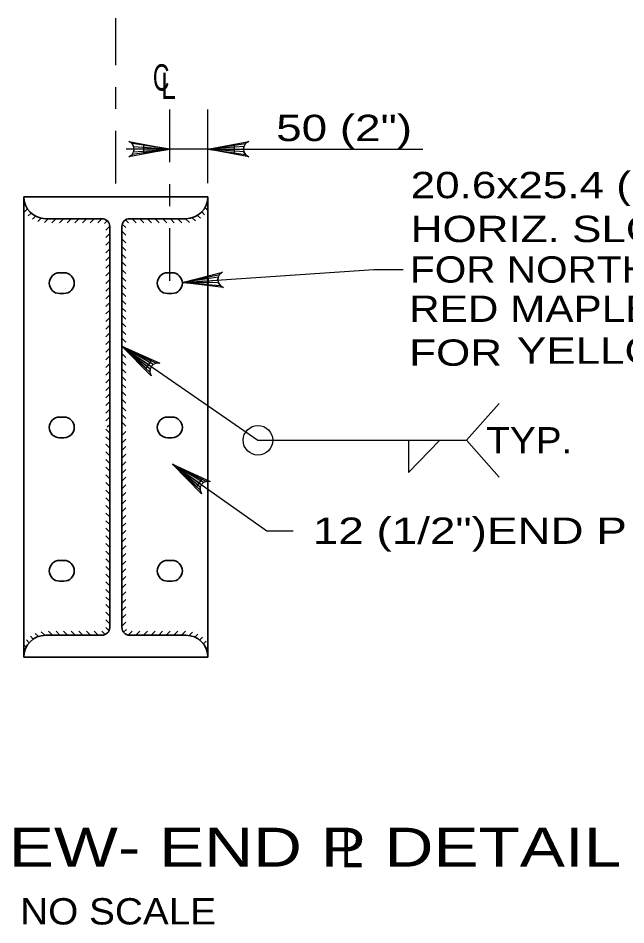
# Model space of a CAD drawing. Extents: x -11 to 79, y -154 to 0.
# Drawn here: x 56.975 to 59.744, y -56.841 to -52.709 of the extents above; entities that cross this region are included whole.
import ezdxf
from ezdxf.enums import TextEntityAlignment as Align

# ---------------------------------------------------------------- set-up
doc = ezdxf.new("R2010")
doc.units = 0
doc.header["$LTSCALE"] = 0.048
doc.linetypes.add('DOT_DASHED', pattern=[7.7, 5, -1.2, 0.3, -1.2])
doc.layers.add('3', color=7, linetype='Continuous', lineweight=25)
doc.layers.add('4', color=7, linetype='Continuous', lineweight=25)

msp = doc.modelspace()

# ---------------------------------------------------------------- hatches: boundary and pattern name
at = {"layer": '3'}
for points in [[(57.546, -53.28558), (57.546, -53.32558), (57.666, -53.30558)], [(57.95925, -53.28558), (57.95925, -53.32558), (57.83925, -53.30558)], [(57.723, -53.91358), (57.84342, -53.91533), (57.84208, -53.89542)], [(57.55825, -54.30467), (57.58133, -54.272), (57.47183, -54.219)], [(57.7895, -54.84425), (57.81258, -54.81158), (57.70308, -54.75867)]]:
    msp.add_hatch(color=256, dxfattribs=at).paths.add_polyline_path(points)

# ---------------------------------------------------------------- linework, layer by layer
at = {"layer": '3', "linetype": 'DOT_DASHED'}
msp.add_line((57.666, -53.90508), (57.666, -53.12558), dxfattribs=at)
at = {"layer": '3'}
for p, q in [((57.83925, -53.46017), (57.83925, -53.12558)), ((57.83925, -53.30558), (57.46642, -53.30558)), ((57.95925, -53.30558), (58.07925, -53.30558)), ((58.07925, -53.30558), (58.8185, -53.30558)), ((57.723, -53.91358), (58.59592, -53.85375)), ((58.59592, -53.85375), (58.72842, -53.85375)), ((57.4475, -54.20375), (58.06767, -54.63258)), ((59.01742, -54.63258), (59.16567, -54.46475)), ((58.06767, -54.63258), (59.01742, -54.63258)), ((59.01742, -54.63258), (59.16567, -54.8005)), ((57.67775, -54.74067), (58.1075, -55.04475)), ((58.1075, -55.04475), (58.2275, -55.04475))]:
    msp.add_line(p, q, dxfattribs=at)
for points in [[(57.666, -53.30558), (57.47958, -53.3405), (57.49392, -53.33058), (57.50133, -53.31808), (57.5035, -53.30558), (57.50133, -53.29308), (57.49392, -53.28058), (57.47958, -53.27067), (57.666, -53.30558), (57.49392, -53.28058), (57.50133, -53.29308), (57.666, -53.30558), (57.5035, -53.30558), (57.50133, -53.31808), (57.666, -53.30558), (57.49392, -53.33058)], [(57.83925, -53.30558), (58.02567, -53.27067), (58.01133, -53.28058), (58.00392, -53.29308), (58.00175, -53.30558), (58.00392, -53.31808), (58.01133, -53.33058), (58.02567, -53.3405), (57.83925, -53.30558), (58.01133, -53.33058), (58.00392, -53.31808), (57.83925, -53.30558), (58.00175, -53.30558), (58.00392, -53.29308), (57.83925, -53.30558), (58.01133, -53.28058)], [(57.723, -53.91358), (57.90658, -53.866), (57.89292, -53.87692), (57.88642, -53.88983), (57.88508, -53.9025), (57.88808, -53.91483), (57.89633, -53.92675), (57.91133, -53.93567), (57.723, -53.91358), (57.89633, -53.92675), (57.88808, -53.91483), (57.723, -53.91358), (57.88508, -53.9025), (57.88642, -53.88983), (57.723, -53.91358), (57.89292, -53.87692)], [(57.4475, -54.20375), (57.62067, -54.281), (57.60325, -54.281), (57.59, -54.28708), (57.58117, -54.29617), (57.57583, -54.30767), (57.57483, -54.32217), (57.58092, -54.3385), (57.4475, -54.20375), (57.57483, -54.32217), (57.57583, -54.30767), (57.4475, -54.20375), (57.58117, -54.29617), (57.59, -54.28708), (57.4475, -54.20375), (57.60325, -54.281)], [(58.754, -54.63258), (58.754, -54.77933), (58.89542, -54.63258)], [(57.67775, -54.74067), (57.85008, -54.81983), (57.83267, -54.81967), (57.81933, -54.82558), (57.81042, -54.8345), (57.80492, -54.846), (57.80375, -54.86042), (57.80975, -54.87683), (57.67775, -54.74067), (57.80375, -54.86042), (57.80492, -54.846), (57.67775, -54.74067), (57.81042, -54.8345), (57.81933, -54.82558), (57.67775, -54.74067), (57.83267, -54.81967)]]:
    msp.add_lwpolyline(points, dxfattribs=at)
for points in [[(57.546, -53.28558), (57.546, -53.32558), (57.666, -53.30558)], [(57.95925, -53.28558), (57.95925, -53.32558), (57.83925, -53.30558)], [(57.723, -53.91358), (57.84342, -53.91533), (57.84208, -53.89542)], [(57.55825, -54.30467), (57.58133, -54.272), (57.47183, -54.219)], [(57.7895, -54.84425), (57.81258, -54.81158), (57.70308, -54.75867)]]:
    msp.add_lwpolyline(points, close=True, dxfattribs=at)
msp.add_circle((58.06763, -54.6326), 0.06746, dxfattribs=at)
at = {"layer": '4', "linetype": 'DOT_DASHED'}
msp.add_line((57.42, -53.46258), (57.42, -52.70858), dxfattribs=at)
at = {"layer": '4', "lineweight": 35}
for p, q in [((57.00067, -53.52267), (57.00067, -55.62108)), ((57.83925, -53.52267), (57.00067, -53.52267)), ((57.83925, -53.52267), (57.83925, -55.62108)), ((57.00467, -53.59142), (57.01767, -53.57842)), ((57.35683, -53.62267), (57.10067, -53.62267)), ((57.73925, -53.62267), (57.48308, -53.62267)), ((57.39242, -53.65825), (57.39242, -55.4855)), ((57.4475, -53.65825), (57.4475, -55.4855)), ((57.16408, -53.86917), (57.18375, -53.86917)), ((57.65617, -53.86917), (57.67592, -53.86917)), ((57.16408, -53.96358), (57.18375, -53.96358)), ((57.65617, -53.96358), (57.67592, -53.96358)), ((57.16408, -54.52658), (57.18375, -54.52658)), ((57.65617, -54.52658), (57.67592, -54.52658)), ((57.16408, -54.62108), (57.18375, -54.62108)), ((57.65617, -54.62108), (57.67592, -54.62108)), ((57.16408, -55.18017), (57.18375, -55.18017)), ((57.65617, -55.18017), (57.67592, -55.18017)), ((57.16408, -55.27467), (57.18375, -55.27467)), ((57.65617, -55.27467), (57.67592, -55.27467)), ((57.35683, -55.52108), (57.10067, -55.52108)), ((57.73925, -55.52108), (57.48308, -55.52108)), ((57.83925, -55.62108), (57.00067, -55.62108))]:
    msp.add_line(p, q, dxfattribs=at)
at = {"layer": '4'}
for p, q in [((57.00067, -53.52583), (57.00075, -53.52575)), ((57.00067, -53.56058), (57.00608, -53.55517)), ((57.83925, -53.54992), (57.83625, -53.54692)), ((57.021, -53.60983), (57.03383, -53.59708)), ((57.82433, -53.60458), (57.8115, -53.59183)), ((57.83925, -53.58475), (57.82633, -53.57183)), ((57.04108, -53.62467), (57.05433, -53.61133)), ((57.06517, -53.63533), (57.08, -53.6205)), ((57.09467, -53.64067), (57.11258, -53.62267)), ((57.12925, -53.64075), (57.14742, -53.62267)), ((57.16408, -53.64075), (57.18217, -53.62267)), ((57.19892, -53.64075), (57.217, -53.62267)), ((57.23367, -53.64075), (57.25183, -53.62267)), ((57.2685, -53.64075), (57.28658, -53.62267)), ((57.30325, -53.64075), (57.32142, -53.62267)), ((57.33808, -53.64075), (57.35617, -53.62267)), ((57.36842, -53.64525), (57.38125, -53.63242)), ((57.47842, -53.64142), (57.46475, -53.62775)), ((57.5125, -53.64075), (57.49442, -53.62267)), ((57.54733, -53.64075), (57.52925, -53.62267)), ((57.58217, -53.64075), (57.564, -53.62267)), ((57.61692, -53.64075), (57.59883, -53.62267)), ((57.65175, -53.64075), (57.63358, -53.62267)), ((57.6865, -53.64075), (57.66842, -53.62267)), ((57.72133, -53.64075), (57.70325, -53.62267)), ((57.75508, -53.63975), (57.738, -53.62267)), ((57.78267, -53.6325), (57.7685, -53.61833)), ((57.80542, -53.6205), (57.79233, -53.60742)), ((57.37433, -53.67417), (57.39233, -53.65608)), ((57.46567, -53.69825), (57.4475, -53.68017)), ((57.46567, -53.6635), (57.44933, -53.64717)), ((57.37433, -53.709), (57.39242, -53.69083)), ((57.46567, -53.73308), (57.4475, -53.715)), ((57.37433, -53.74375), (57.39242, -53.72567)), ((57.37433, -53.77858), (57.39242, -53.76042)), ((57.46567, -53.76792), (57.4475, -53.74975)), ((57.37433, -53.81333), (57.39242, -53.79525)), ((57.46567, -53.80267), (57.4475, -53.78458)), ((57.37433, -53.84817), (57.39242, -53.83008)), ((57.46567, -53.8375), (57.4475, -53.81933)), ((57.37433, -53.88292), (57.39242, -53.86483)), ((57.46567, -53.87225), (57.4475, -53.85417)), ((57.37433, -53.91775), (57.39242, -53.89967)), ((57.46567, -53.90708), (57.4475, -53.889)), ((57.46567, -53.94192), (57.4475, -53.92375)), ((57.37433, -53.95258), (57.39242, -53.93442)), ((57.37433, -53.98733), (57.39242, -53.96925)), ((57.46567, -53.97667), (57.4475, -53.95858)), ((57.37433, -54.02217), (57.39242, -54.004)), ((57.46567, -54.0115), (57.4475, -53.99333)), ((57.37433, -54.05692), (57.39242, -54.03883)), ((57.46567, -54.04625), (57.4475, -54.02817)), ((57.37433, -54.09175), (57.39242, -54.07367)), ((57.46567, -54.08108), (57.4475, -54.063)), ((57.37433, -54.12658), (57.39242, -54.10842)), ((57.46567, -54.11583), (57.4475, -54.09775)), ((57.46567, -54.15067), (57.4475, -54.13258)), ((57.37433, -54.16133), (57.39242, -54.14325)), ((57.46567, -54.1855), (57.4475, -54.16733)), ((57.37433, -54.19617), (57.39242, -54.178)), ((57.37433, -54.23092), (57.39242, -54.21283)), ((57.46567, -54.22025), (57.4475, -54.20217)), ((57.37433, -54.26575), (57.39242, -54.24767)), ((57.46567, -54.25508), (57.4475, -54.23692)), ((57.37433, -54.3005), (57.39242, -54.28242)), ((57.46567, -54.28983), (57.4475, -54.27175)), ((57.37433, -54.33533), (57.39242, -54.31725)), ((57.46567, -54.32467), (57.4475, -54.30658)), ((57.46567, -54.3595), (57.4475, -54.34133)), ((57.37433, -54.37017), (57.39242, -54.352)), ((57.46567, -54.39425), (57.4475, -54.37617)), ((57.37433, -54.40492), (57.39242, -54.38683)), ((57.37433, -54.43975), (57.39242, -54.42158)), ((57.46567, -54.42908), (57.4475, -54.41092)), ((57.37433, -54.4745), (57.39242, -54.45642)), ((57.46567, -54.46383), (57.4475, -54.44575)), ((57.37433, -54.50933), (57.39242, -54.49125)), ((57.46567, -54.49867), (57.4475, -54.48058)), ((57.37433, -54.54408), (57.39242, -54.526)), ((57.46567, -54.53342), (57.4475, -54.51533)), ((57.39242, -54.59942), (57.37433, -54.58133)), ((57.38133, -54.57192), (57.39242, -54.56083)), ((57.46567, -54.56825), (57.4475, -54.55017)), ((57.4475, -54.57525), (57.45092, -54.57192)), ((57.39242, -54.63425), (57.37433, -54.61608)), ((57.4475, -54.61008), (57.46567, -54.592)), ((57.4475, -54.64492), (57.46567, -54.62675)), ((57.39242, -54.669), (57.37433, -54.65092)), ((57.4475, -54.67967), (57.46567, -54.66158)), ((57.39242, -54.70383), (57.37433, -54.68567)), ((57.4475, -54.7145), (57.46567, -54.69642)), ((57.39242, -54.73858), (57.37433, -54.7205)), ((57.4475, -54.74925), (57.46567, -54.73117)), ((57.39242, -54.77342), (57.37433, -54.75533)), ((57.39242, -54.80825), (57.37433, -54.79008)), ((57.4475, -54.78408), (57.46567, -54.766)), ((57.39242, -54.843), (57.37433, -54.82492)), ((57.4475, -54.81892), (57.46567, -54.80075)), ((57.4475, -54.85367), (57.46567, -54.83558)), ((57.39242, -54.87783), (57.37433, -54.85967)), ((57.4475, -54.8885), (57.46567, -54.87033)), ((57.39242, -54.91258), (57.37433, -54.8945)), ((57.4475, -54.92325), (57.46567, -54.90517)), ((57.39242, -54.94742), (57.37433, -54.92933)), ((57.4475, -54.95808), (57.46567, -54.94)), ((57.39242, -54.98217), (57.37433, -54.96408)), ((57.39242, -55.017), (57.37433, -54.99892)), ((57.4475, -54.99283), (57.46567, -54.97475)), ((57.39242, -55.05183), (57.37433, -55.03367)), ((57.4475, -55.02767), (57.46567, -55.00958)), ((57.39242, -55.08658), (57.37433, -55.0685)), ((57.4475, -55.0625), (57.46567, -55.04433)), ((57.4475, -55.09725), (57.46567, -55.07917)), ((57.39242, -55.12142), (57.37433, -55.10325)), ((57.4475, -55.13208), (57.46567, -55.11392)), ((57.39242, -55.15617), (57.37433, -55.13808)), ((57.4475, -55.16683), (57.46567, -55.14875)), ((57.39242, -55.191), (57.37433, -55.17292)), ((57.39242, -55.22583), (57.37433, -55.20767)), ((57.4475, -55.20167), (57.46567, -55.18358)), ((57.39242, -55.26058), (57.37433, -55.2425)), ((57.4475, -55.2365), (57.46567, -55.21833)), ((57.39242, -55.29542), (57.37433, -55.27725)), ((57.4475, -55.27125), (57.46567, -55.25317)), ((57.4475, -55.30608), (57.46567, -55.28792)), ((57.39242, -55.33017), (57.37433, -55.31208)), ((57.4475, -55.34083), (57.46567, -55.32275)), ((57.39242, -55.365), (57.37433, -55.34692)), ((57.4475, -55.37567), (57.46567, -55.35758)), ((57.39242, -55.39975), (57.37433, -55.38167)), ((57.4475, -55.41042), (57.46567, -55.39233)), ((57.39242, -55.43458), (57.37433, -55.4165)), ((57.39242, -55.46942), (57.37433, -55.45125)), ((57.4475, -55.44525), (57.46567, -55.42717)), ((57.389, -55.50075), (57.37433, -55.48608)), ((57.4475, -55.48008), (57.46567, -55.46192)), ((57.455, -55.50733), (57.468, -55.49433)), ((57.04408, -55.53867), (57.03108, -55.52567)), ((57.06717, -55.52692), (57.05317, -55.51292)), ((57.09625, -55.52117), (57.07992, -55.50483)), ((57.13092, -55.52108), (57.11283, -55.503)), ((57.16575, -55.52108), (57.14767, -55.503)), ((57.20058, -55.52108), (57.18242, -55.503)), ((57.23533, -55.52108), (57.21725, -55.503)), ((57.27017, -55.52108), (57.252, -55.503)), ((57.30492, -55.52108), (57.28683, -55.503)), ((57.33975, -55.52108), (57.32167, -55.503)), ((57.37142, -55.518), (57.35642, -55.503)), ((57.47667, -55.5205), (57.49417, -55.503)), ((57.51092, -55.52108), (57.529, -55.503)), ((57.54567, -55.52108), (57.56375, -55.503)), ((57.5805, -55.52108), (57.59858, -55.503)), ((57.61525, -55.52108), (57.63342, -55.503)), ((57.65008, -55.52108), (57.66817, -55.503)), ((57.68483, -55.52108), (57.703, -55.503)), ((57.71967, -55.52108), (57.73775, -55.503)), ((57.7535, -55.52208), (57.76883, -55.50675)), ((57.78042, -55.52992), (57.79392, -55.51642)), ((57.802, -55.54317), (57.81483, -55.53033)), ((57.01158, -55.57575), (57.00067, -55.56483)), ((57.02567, -55.555), (57.01283, -55.54217)), ((57.81908, -55.56083), (57.832, -55.548)), ((57.83175, -55.583), (57.83925, -55.5755)), ((57.00258, -55.60158), (57.00067, -55.59967)), ((57.83875, -55.61083), (57.83925, -55.61033))]:
    msp.add_line(p, q, dxfattribs=at)
at = {"layer": '4', "lineweight": 35}
for centre, radius, start, end in [((57.10069, -53.52267), 0.1, 180, 270), ((57.73927, -53.52267), 0.1, 270, 0), ((57.35684, -53.65824), 0.03558, 0, 90), ((57.48311, -53.65824), 0.03558, 90, 180), ((57.16407, -53.91637), 0.04724, 90, 270), ((57.18376, -53.91637), 0.04724, 270, 90), ((57.6562, -53.91637), 0.04724, 90, 270), ((57.67588, -53.91637), 0.04724, 270, 90), ((57.16407, -54.57384), 0.04724, 90, 270), ((57.18376, -54.57384), 0.04724, 270, 90), ((57.6562, -54.57384), 0.04724, 90, 270), ((57.67588, -54.57384), 0.04724, 270, 90), ((57.16407, -55.22739), 0.04724, 90, 270), ((57.18376, -55.22739), 0.04724, 270, 90), ((57.6562, -55.22739), 0.04724, 90, 270), ((57.67588, -55.22739), 0.04724, 270, 90), ((57.35684, -55.48551), 0.03558, 270, 0), ((57.48311, -55.48551), 0.03558, 180, 270), ((57.10069, -55.62109), 0.1, 90, 180), ((57.73927, -55.62109), 0.1, 0, 90)]:
    msp.add_arc(centre, radius, start, end, dxfattribs=at)

# ---------------------------------------------------------------- texts
at = {"layer": '3'}
for s, width, p in [('C', 0.65, (57.58883, -53.03875)), ('L', 0.75, (57.6265, -53.0765)), ('20.6x25.4 (13/16"x1")', 1.25, (58.76308, -53.52925)), ('HORIZ. SLOTTED HOLE', 1.25, (58.76308, -53.72925)), ('FOR NORTHERN RED OAK AND', 1.15, (58.76033, -53.914)), ('RED MAPLE.  27.0x33.3 (1 1/16"x1 5/16")', 1.2, (58.75625, -54.093)), ('FOR ', 1.25, (58.75625, -54.293)), ('YELLOW POPLAR. (TYP.)', 1.25, (59.24708, -54.28383)), ('TYP.', 1.1, (59.10742, -54.69258)), ('12 (1/2")END P', 1.3, (58.3175, -55.10467)), ('NO SCALE', 1.1, (56.98433, -56.83933))]:
    msp.add_text(s, height=0.12, dxfattribs=dict(at, width=width)).set_placement(p)
at = {"layer": '3', "width": 1.3}
for s, height, p in [('50 (2")', 0.12, (58.46012, -53.26892)), ('SECTION VIEW- END P DETAIL', 0.1772, (57.455, -56.57558))]:
    msp.add_text(s, height=height, dxfattribs=at).set_placement(p, align=Align.CENTER)
at = {"layer": '4', "width": 0.75}
msp.add_text('L', height=0.1772, dxfattribs=at).set_placement((58.49583, -56.57925), align=Align.CENTER)

doc.saveas('drawing.dxf')
